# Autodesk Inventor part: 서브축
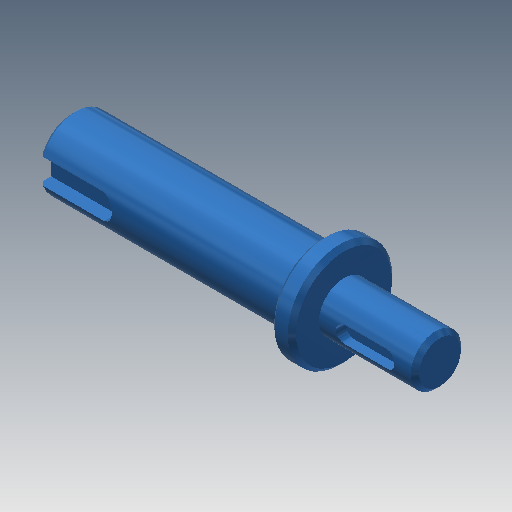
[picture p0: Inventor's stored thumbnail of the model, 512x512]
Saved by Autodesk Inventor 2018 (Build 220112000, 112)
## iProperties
Created: 2018-09
Part Number: 서브축
Document SubType Name: Modeling
Density: 7.86 g/cm^3
Material: 강철, 연강
Mass: 142.801 g
Surface Area: 54.794 cm^2
Volume: 18.1681 cm^3
Appearance: 청록색
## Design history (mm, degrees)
sketch "스케치1"
  geometry: L1 (-18.818, -7)-(-18.818, 7) reference; L2 (-41.331, -13.5)-(-41.331, 13.5) reference; L3 (-46.5, 12.249)-(-46.5, -12.249) reference; L4 (-18.331, 0)-(-106.5, 0); L5 (-18.331, 0)-(-18.331, -6); L6 (-18.331, -6)-(-41.331, -6); L7 (-41.331, -12.5)-(-46.5, -12.5); L8 (-46.5, -8.5)-(-106.5, -8.5); L9 (-106.5, -8.5)-(-106.5, 0); L10 (-46.5, -8.5)-(-46.5, -12.5); L11 (-41.331, -6)-(-41.331, -12.5); 2 further points
  constraints: 17 end point, 5 point on line, 3 parallel, 3 perpendicular, 2 collinear, 1 midpoint
  dimensions: "d0" = 23 distance between parallel lines of L2 L5; "d1" = 12 diameter of L6 L4; "d2" = 25 diameter of L7 L4; "d3" = 17 diameter of L8 L4; "d4" = 60 distance of L8.start L8.end
revolve "회전1" sketch "스케치1" stored, may be unused: angle "d5" = 90 deg
chamfer "모따기1" distance "d6" = 1; stored, may be unused: second distance "d7" = 2, angle "d8" = 45 deg
node "작업 평면1"
sketch "스케치2"
  geometry: L1 (11.5, 5)-(11.5, -5) reference; L2 (-5.5, -2)-(4.5, -2); L3 (4.5, 2)-(-5.5, 2); A1 r 2 centre (4.5, 0) between (4.5, -2) and (4.5, 2); A2 r 2 centre (-5.5, 0) between (-5.5, 2) and (-5.5, -2); 2 further points
  constraints: 4 end point, 4 point on circle, 4 tangent, 2 centre point, 1 horizontal alignment, 1 midpoint, 1 parallel, 1 perpendicular
  dimensions: "d9" = 4 distance between parallel lines of L2 L3; "d10" = 14 dimension on A1 A2; "d11" = 5 distance edge to line of A1 L1
extrude "돌출1" cut sketch "스케치2" distance "d12" = 2.5; taper "d13" = 0 deg
node "작업 평면2"
sketch "스케치3"
  geometry: L1 (-30, -7.5)-(-30, 7.5) reference; L2 (-30, 3)-(-15, 3); L3 (-15, -3)-(-30, -3); A1 r 3 centre (-15, 0) between (-15, -3) and (-15, 3); 2 further points
  constraints: 4 end point, 2 perpendicular, 2 point on circle, 2 point on line, 2 tangent, 1 centre point, 1 horizontal alignment, 1 midpoint
  dimensions: "d14" = 6 distance between parallel lines of L3 L2; "d15" = 18 dimension on A1 L1
extrude "돌출2" cut sketch "스케치3" distance "d16" = 3.5; taper "d17" = 0 deg
node "솔리드1"
node "참조1"
node "참조2"
node "참조3"
